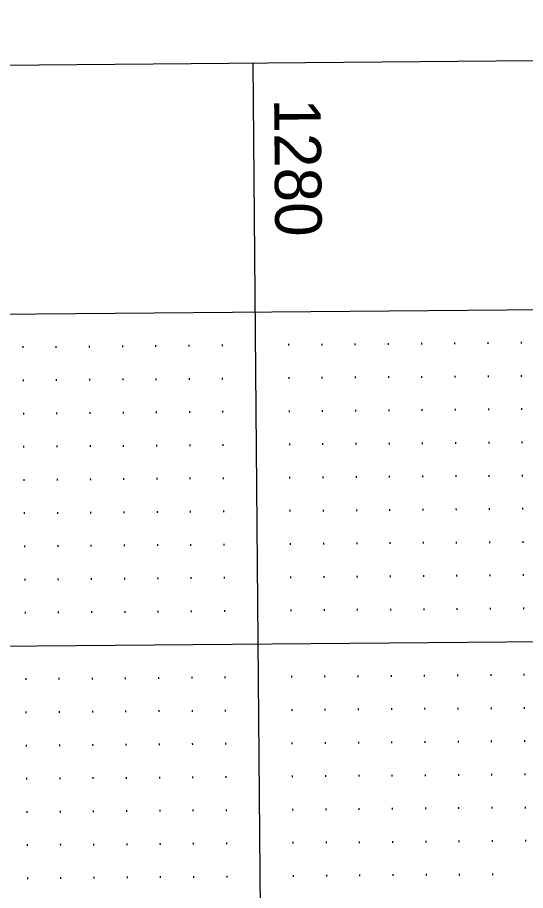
# Model space of a CAD drawing. Extents: x 2149873 to 2152007, y 140538 to 142349.
# Drawn here: x 2150190.3 to 2150266.8, y 142037.2 to 142168.7 of the extents above; entities that cross this region are included whole.
import ezdxf

# ---------------------------------------------------------------- set-up
doc = ezdxf.new("R2010")
doc.units = 0
for name, color, linetype in [('SHT_Plan_Profile_Sheet_Elev_Txt', 7, 'Continuous'), ('SHT_Profile_Grid_Major', 7, 'Continuous'), ('SHT_Profile_Grid_Minor', 7, 'Continuous'), ('SHT_Sheet_Border', 7, 'Continuous')]:
    doc.layers.add(name, color=color, linetype=linetype)

msp = doc.modelspace()

# ---------------------------------------------------------------- linework, layer by layer
at = {"layer": 'SHT_Profile_Grid_Major'}
for p, q in [((2150225.72, 142161.82), (2150239.5, 140586.88)), ((2149976.49, 142072.13), (2150476.47, 142076.51))]:
    msp.add_line(p, q, dxfattribs=at)
at = {"layer": 'SHT_Profile_Grid_Minor'}
for p, q in [((2150191.09, 142119.14), (2150191.09, 142118.89)), ((2150196.09, 142119.18), (2150196.09, 142118.93)), ((2150201.09, 142119.23), (2150201.09, 142118.98)), ((2150206.09, 142119.27), (2150206.09, 142119.02)), ((2150211.09, 142119.31), (2150211.09, 142119.06)), ((2150216.09, 142119.36), (2150216.09, 142119.11)), ((2150221.09, 142119.4), (2150221.09, 142119.15)), ((2150231.09, 142119.49), (2150231.09, 142119.24)), ((2150236.09, 142119.53), (2150236.09, 142119.28)), ((2150241.09, 142119.58), (2150241.09, 142119.33)), ((2150246.09, 142119.62), (2150246.09, 142119.37)), ((2150251.09, 142119.66), (2150251.09, 142119.41)), ((2150256.09, 142119.71), (2150256.09, 142119.46)), ((2150261.09, 142119.75), (2150261.09, 142119.5)), ((2150266.09, 142119.8), (2150266.09, 142119.55)), ((2150191.13, 142114.14), (2150191.13, 142113.89)), ((2150196.13, 142114.18), (2150196.13, 142113.93)), ((2150201.13, 142114.23), (2150201.13, 142113.98)), ((2150206.13, 142114.27), (2150206.13, 142114.02)), ((2150211.13, 142114.31), (2150211.13, 142114.06)), ((2150216.13, 142114.36), (2150216.13, 142114.11)), ((2150221.13, 142114.4), (2150221.13, 142114.15)), ((2150231.13, 142114.49), (2150231.13, 142114.24)), ((2150236.13, 142114.53), (2150236.13, 142114.28)), ((2150241.13, 142114.58), (2150241.13, 142114.33)), ((2150246.13, 142114.62), (2150246.13, 142114.37)), ((2150251.13, 142114.66), (2150251.13, 142114.41)), ((2150256.13, 142114.71), (2150256.13, 142114.46)), ((2150261.13, 142114.75), (2150261.13, 142114.5)), ((2150266.13, 142114.8), (2150266.13, 142114.55)), ((2150191.18, 142109.14), (2150191.18, 142108.89)), ((2150196.18, 142109.18), (2150196.18, 142108.93)), ((2150201.18, 142109.23), (2150201.18, 142108.98)), ((2150206.18, 142109.27), (2150206.18, 142109.02)), ((2150211.18, 142109.32), (2150211.18, 142109.07)), ((2150216.18, 142109.36), (2150216.18, 142109.11)), ((2150221.17, 142109.4), (2150221.18, 142109.15)), ((2150231.17, 142109.49), (2150231.18, 142109.24)), ((2150236.17, 142109.53), (2150236.18, 142109.28)), ((2150241.17, 142109.58), (2150241.18, 142109.33)), ((2150246.17, 142109.62), (2150246.18, 142109.37)), ((2150251.17, 142109.67), (2150251.18, 142109.42)), ((2150256.17, 142109.71), (2150256.18, 142109.46)), ((2150261.17, 142109.75), (2150261.18, 142109.5)), ((2150266.17, 142109.8), (2150266.18, 142109.55)), ((2150241.22, 142104.58), (2150241.22, 142104.33)), ((2150246.22, 142104.62), (2150246.22, 142104.37)), ((2150251.22, 142104.67), (2150251.22, 142104.42)), ((2150256.22, 142104.71), (2150256.22, 142104.46)), ((2150261.22, 142104.75), (2150261.22, 142104.5)), ((2150266.22, 142104.8), (2150266.22, 142104.55)), ((2150191.22, 142104.14), (2150191.22, 142103.89)), ((2150196.22, 142104.18), (2150196.22, 142103.93)), ((2150201.22, 142104.23), (2150201.22, 142103.98)), ((2150206.22, 142104.27), (2150206.22, 142104.02)), ((2150211.22, 142104.32), (2150211.22, 142104.07)), ((2150216.22, 142104.36), (2150216.22, 142104.11)), ((2150221.22, 142104.4), (2150221.22, 142104.15)), ((2150231.22, 142104.49), (2150231.22, 142104.24)), ((2150236.22, 142104.53), (2150236.22, 142104.28)), ((2150211.26, 142099.32), (2150211.27, 142099.07)), ((2150216.26, 142099.36), (2150216.26, 142099.11)), ((2150221.26, 142099.4), (2150221.26, 142099.15)), ((2150231.26, 142099.49), (2150231.26, 142099.24)), ((2150236.26, 142099.53), (2150236.26, 142099.28)), ((2150241.26, 142099.58), (2150241.26, 142099.33)), ((2150246.26, 142099.62), (2150246.26, 142099.37)), ((2150251.26, 142099.67), (2150251.26, 142099.42)), ((2150256.26, 142099.71), (2150256.26, 142099.46)), ((2150261.26, 142099.75), (2150261.26, 142099.5)), ((2150266.26, 142099.8), (2150266.26, 142099.55)), ((2150191.26, 142099.14), (2150191.27, 142098.89)), ((2150196.26, 142099.18), (2150196.27, 142098.93)), ((2150201.26, 142099.23), (2150201.27, 142098.98)), ((2150206.26, 142099.27), (2150206.27, 142099.02)), ((2150191.31, 142094.14), (2150191.31, 142093.89)), ((2150196.31, 142094.18), (2150196.31, 142093.93)), ((2150201.31, 142094.23), (2150201.31, 142093.98)), ((2150206.31, 142094.27), (2150206.31, 142094.02)), ((2150211.31, 142094.32), (2150211.31, 142094.07)), ((2150216.31, 142094.36), (2150216.31, 142094.11)), ((2150221.31, 142094.4), (2150221.31, 142094.15)), ((2150231.31, 142094.49), (2150231.31, 142094.24)), ((2150236.31, 142094.53), (2150236.31, 142094.28)), ((2150241.31, 142094.58), (2150241.31, 142094.33)), ((2150246.31, 142094.62), (2150246.31, 142094.37)), ((2150251.31, 142094.67), (2150251.31, 142094.42)), ((2150256.3, 142094.71), (2150256.31, 142094.46)), ((2150261.3, 142094.75), (2150261.31, 142094.5)), ((2150266.3, 142094.8), (2150266.31, 142094.55)), ((2150191.35, 142089.14), (2150191.35, 142088.89)), ((2150196.35, 142089.18), (2150196.35, 142088.93)), ((2150201.35, 142089.23), (2150201.35, 142088.98)), ((2150206.35, 142089.27), (2150206.35, 142089.02)), ((2150211.35, 142089.32), (2150211.35, 142089.07)), ((2150216.35, 142089.36), (2150216.35, 142089.11)), ((2150221.35, 142089.4), (2150221.35, 142089.15)), ((2150231.35, 142089.49), (2150231.35, 142089.24)), ((2150236.35, 142089.53), (2150236.35, 142089.28)), ((2150241.35, 142089.58), (2150241.35, 142089.33)), ((2150246.35, 142089.62), (2150246.35, 142089.37)), ((2150251.35, 142089.67), (2150251.35, 142089.42)), ((2150256.35, 142089.71), (2150256.35, 142089.46)), ((2150261.35, 142089.75), (2150261.35, 142089.5)), ((2150266.35, 142089.8), (2150266.35, 142089.55)), ((2150191.4, 142084.14), (2150191.4, 142083.89)), ((2150196.39, 142084.18), (2150196.4, 142083.93)), ((2150201.39, 142084.23), (2150201.4, 142083.98)), ((2150206.39, 142084.27), (2150206.4, 142084.02)), ((2150211.39, 142084.32), (2150211.4, 142084.07)), ((2150216.39, 142084.36), (2150216.4, 142084.11)), ((2150221.39, 142084.4), (2150221.4, 142084.15)), ((2150231.39, 142084.49), (2150231.4, 142084.24)), ((2150236.39, 142084.53), (2150236.4, 142084.28)), ((2150241.39, 142084.58), (2150241.4, 142084.33)), ((2150246.39, 142084.62), (2150246.4, 142084.37)), ((2150251.39, 142084.67), (2150251.39, 142084.42)), ((2150256.39, 142084.71), (2150256.39, 142084.46)), ((2150261.39, 142084.75), (2150261.39, 142084.5)), ((2150266.39, 142084.8), (2150266.39, 142084.55)), ((2150241.44, 142079.58), (2150241.44, 142079.33)), ((2150246.44, 142079.62), (2150246.44, 142079.37)), ((2150251.44, 142079.67), (2150251.44, 142079.42)), ((2150256.44, 142079.71), (2150256.44, 142079.46)), ((2150261.44, 142079.75), (2150261.44, 142079.5)), ((2150266.44, 142079.8), (2150266.44, 142079.55)), ((2150191.44, 142079.14), (2150191.44, 142078.89)), ((2150196.44, 142079.18), (2150196.44, 142078.93)), ((2150201.44, 142079.23), (2150201.44, 142078.98)), ((2150206.44, 142079.27), (2150206.44, 142079.02)), ((2150211.44, 142079.32), (2150211.44, 142079.07)), ((2150216.44, 142079.36), (2150216.44, 142079.11)), ((2150221.44, 142079.4), (2150221.44, 142079.15)), ((2150231.44, 142079.49), (2150231.44, 142079.24)), ((2150236.44, 142079.54), (2150236.44, 142079.29)), ((2150191.53, 142069.14), (2150191.53, 142068.89)), ((2150196.53, 142069.19), (2150196.53, 142068.94)), ((2150201.53, 142069.23), (2150201.53, 142068.98)), ((2150206.53, 142069.27), (2150206.53, 142069.02)), ((2150211.53, 142069.32), (2150211.53, 142069.07)), ((2150216.53, 142069.36), (2150216.53, 142069.11)), ((2150221.53, 142069.4), (2150221.53, 142069.15)), ((2150231.52, 142069.49), (2150231.53, 142069.24)), ((2150236.52, 142069.54), (2150236.53, 142069.29)), ((2150241.52, 142069.58), (2150241.53, 142069.33)), ((2150246.52, 142069.62), (2150246.53, 142069.37)), ((2150251.52, 142069.67), (2150251.53, 142069.42)), ((2150256.52, 142069.71), (2150256.53, 142069.46)), ((2150261.52, 142069.75), (2150261.53, 142069.5)), ((2150266.52, 142069.8), (2150266.53, 142069.55)), ((2150191.57, 142064.14), (2150191.57, 142063.89)), ((2150196.57, 142064.19), (2150196.57, 142063.94)), ((2150201.57, 142064.23), (2150201.57, 142063.98)), ((2150206.57, 142064.27), (2150206.57, 142064.02)), ((2150211.57, 142064.32), (2150211.57, 142064.07)), ((2150216.57, 142064.36), (2150216.57, 142064.11)), ((2150221.57, 142064.4), (2150221.57, 142064.15)), ((2150231.57, 142064.49), (2150231.57, 142064.24)), ((2150236.57, 142064.54), (2150236.57, 142064.29)), ((2150241.57, 142064.58), (2150241.57, 142064.33)), ((2150246.57, 142064.62), (2150246.57, 142064.37)), ((2150251.57, 142064.67), (2150251.57, 142064.42)), ((2150256.57, 142064.71), (2150256.57, 142064.46)), ((2150261.57, 142064.75), (2150261.57, 142064.5)), ((2150266.57, 142064.8), (2150266.57, 142064.55)), ((2150191.61, 142059.14), (2150191.62, 142058.89)), ((2150196.61, 142059.19), (2150196.62, 142058.94)), ((2150201.61, 142059.23), (2150201.62, 142058.98)), ((2150206.61, 142059.27), (2150206.62, 142059.02)), ((2150211.61, 142059.32), (2150211.62, 142059.07)), ((2150216.61, 142059.36), (2150216.62, 142059.11)), ((2150221.61, 142059.4), (2150221.61, 142059.15)), ((2150231.61, 142059.49), (2150231.61, 142059.24)), ((2150236.61, 142059.54), (2150236.61, 142059.29)), ((2150241.61, 142059.58), (2150241.61, 142059.33)), ((2150246.61, 142059.62), (2150246.61, 142059.37)), ((2150251.61, 142059.67), (2150251.61, 142059.42)), ((2150256.61, 142059.71), (2150256.61, 142059.46)), ((2150261.61, 142059.75), (2150261.61, 142059.5)), ((2150266.61, 142059.8), (2150266.61, 142059.55)), ((2150246.66, 142054.62), (2150246.66, 142054.37)), ((2150251.66, 142054.67), (2150251.66, 142054.42)), ((2150256.66, 142054.71), (2150256.66, 142054.46)), ((2150261.65, 142054.75), (2150261.66, 142054.5)), ((2150266.65, 142054.8), (2150266.66, 142054.55)), ((2150191.66, 142054.14), (2150191.66, 142053.89)), ((2150196.66, 142054.19), (2150196.66, 142053.94)), ((2150201.66, 142054.23), (2150201.66, 142053.98)), ((2150206.66, 142054.27), (2150206.66, 142054.02)), ((2150211.66, 142054.32), (2150211.66, 142054.07)), ((2150216.66, 142054.36), (2150216.66, 142054.11)), ((2150221.66, 142054.4), (2150221.66, 142054.15)), ((2150231.66, 142054.49), (2150231.66, 142054.24)), ((2150236.66, 142054.54), (2150236.66, 142054.29)), ((2150241.66, 142054.58), (2150241.66, 142054.33)), ((2150216.7, 142049.36), (2150216.7, 142049.11)), ((2150221.7, 142049.4), (2150221.7, 142049.15)), ((2150231.7, 142049.49), (2150231.7, 142049.24)), ((2150236.7, 142049.54), (2150236.7, 142049.29)), ((2150241.7, 142049.58), (2150241.7, 142049.33)), ((2150246.7, 142049.62), (2150246.7, 142049.37)), ((2150251.7, 142049.67), (2150251.7, 142049.42)), ((2150256.7, 142049.71), (2150256.7, 142049.46)), ((2150261.7, 142049.76), (2150261.7, 142049.51)), ((2150266.7, 142049.8), (2150266.7, 142049.55)), ((2150191.7, 142049.14), (2150191.7, 142048.89)), ((2150196.7, 142049.19), (2150196.7, 142048.94)), ((2150201.7, 142049.23), (2150201.7, 142048.98)), ((2150206.7, 142049.27), (2150206.7, 142049.02)), ((2150211.7, 142049.32), (2150211.7, 142049.07)), ((2150191.75, 142044.14), (2150191.75, 142043.89)), ((2150196.74, 142044.19), (2150196.75, 142043.94)), ((2150201.74, 142044.23), (2150201.75, 142043.98)), ((2150206.74, 142044.27), (2150206.75, 142044.02)), ((2150211.74, 142044.32), (2150211.75, 142044.07)), ((2150216.74, 142044.36), (2150216.75, 142044.11)), ((2150221.74, 142044.41), (2150221.75, 142044.16)), ((2150231.74, 142044.49), (2150231.75, 142044.24)), ((2150236.74, 142044.54), (2150236.75, 142044.29)), ((2150241.74, 142044.58), (2150241.75, 142044.33)), ((2150246.74, 142044.62), (2150246.75, 142044.37)), ((2150251.74, 142044.67), (2150251.74, 142044.42)), ((2150256.74, 142044.71), (2150256.74, 142044.46)), ((2150261.74, 142044.76), (2150261.74, 142044.51)), ((2150266.74, 142044.8), (2150266.74, 142044.55)), ((2150191.79, 142039.14), (2150191.79, 142038.89)), ((2150196.79, 142039.19), (2150196.79, 142038.94)), ((2150201.79, 142039.23), (2150201.79, 142038.98)), ((2150206.79, 142039.27), (2150206.79, 142039.02)), ((2150211.79, 142039.32), (2150211.79, 142039.07)), ((2150216.79, 142039.36), (2150216.79, 142039.11)), ((2150221.79, 142039.41), (2150221.79, 142039.16)), ((2150231.79, 142039.49), (2150231.79, 142039.24)), ((2150236.79, 142039.54), (2150236.79, 142039.29)), ((2150241.79, 142039.58), (2150241.79, 142039.33)), ((2150246.79, 142039.62), (2150246.79, 142039.37)), ((2150251.79, 142039.67), (2150251.79, 142039.42)), ((2150256.79, 142039.71), (2150256.79, 142039.46)), ((2150261.79, 142039.76), (2150261.79, 142039.51))]:
    msp.add_line(p, q, dxfattribs=at)
at = {"layer": 'SHT_Sheet_Border'}
msp.add_line((2149976.05, 142122.13), (2150476.04, 142126.51), dxfattribs=at)
msp.add_lwpolyline([(2151008.19, 142168.67), (2151021.97, 140593.73), (2149972.01, 140584.54), (2149958.23, 142159.48)], close=True, dxfattribs=at)

# ---------------------------------------------------------------- texts
at = {"layer": 'SHT_Plan_Profile_Sheet_Elev_Txt'}
msp.add_text('1280', height=7, rotation=270.5015, dxfattribs=at).set_placement((2150228.92, 142156.45))

doc.saveas('drawing.dxf')
